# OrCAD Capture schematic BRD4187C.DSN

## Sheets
1 02: RF, Antenna and Power: size A3; title: EFR32xG24B 2.4 GHz 20 dBm Radio Board; rev: A01; company: Silicon Labs; note: BRD4187C
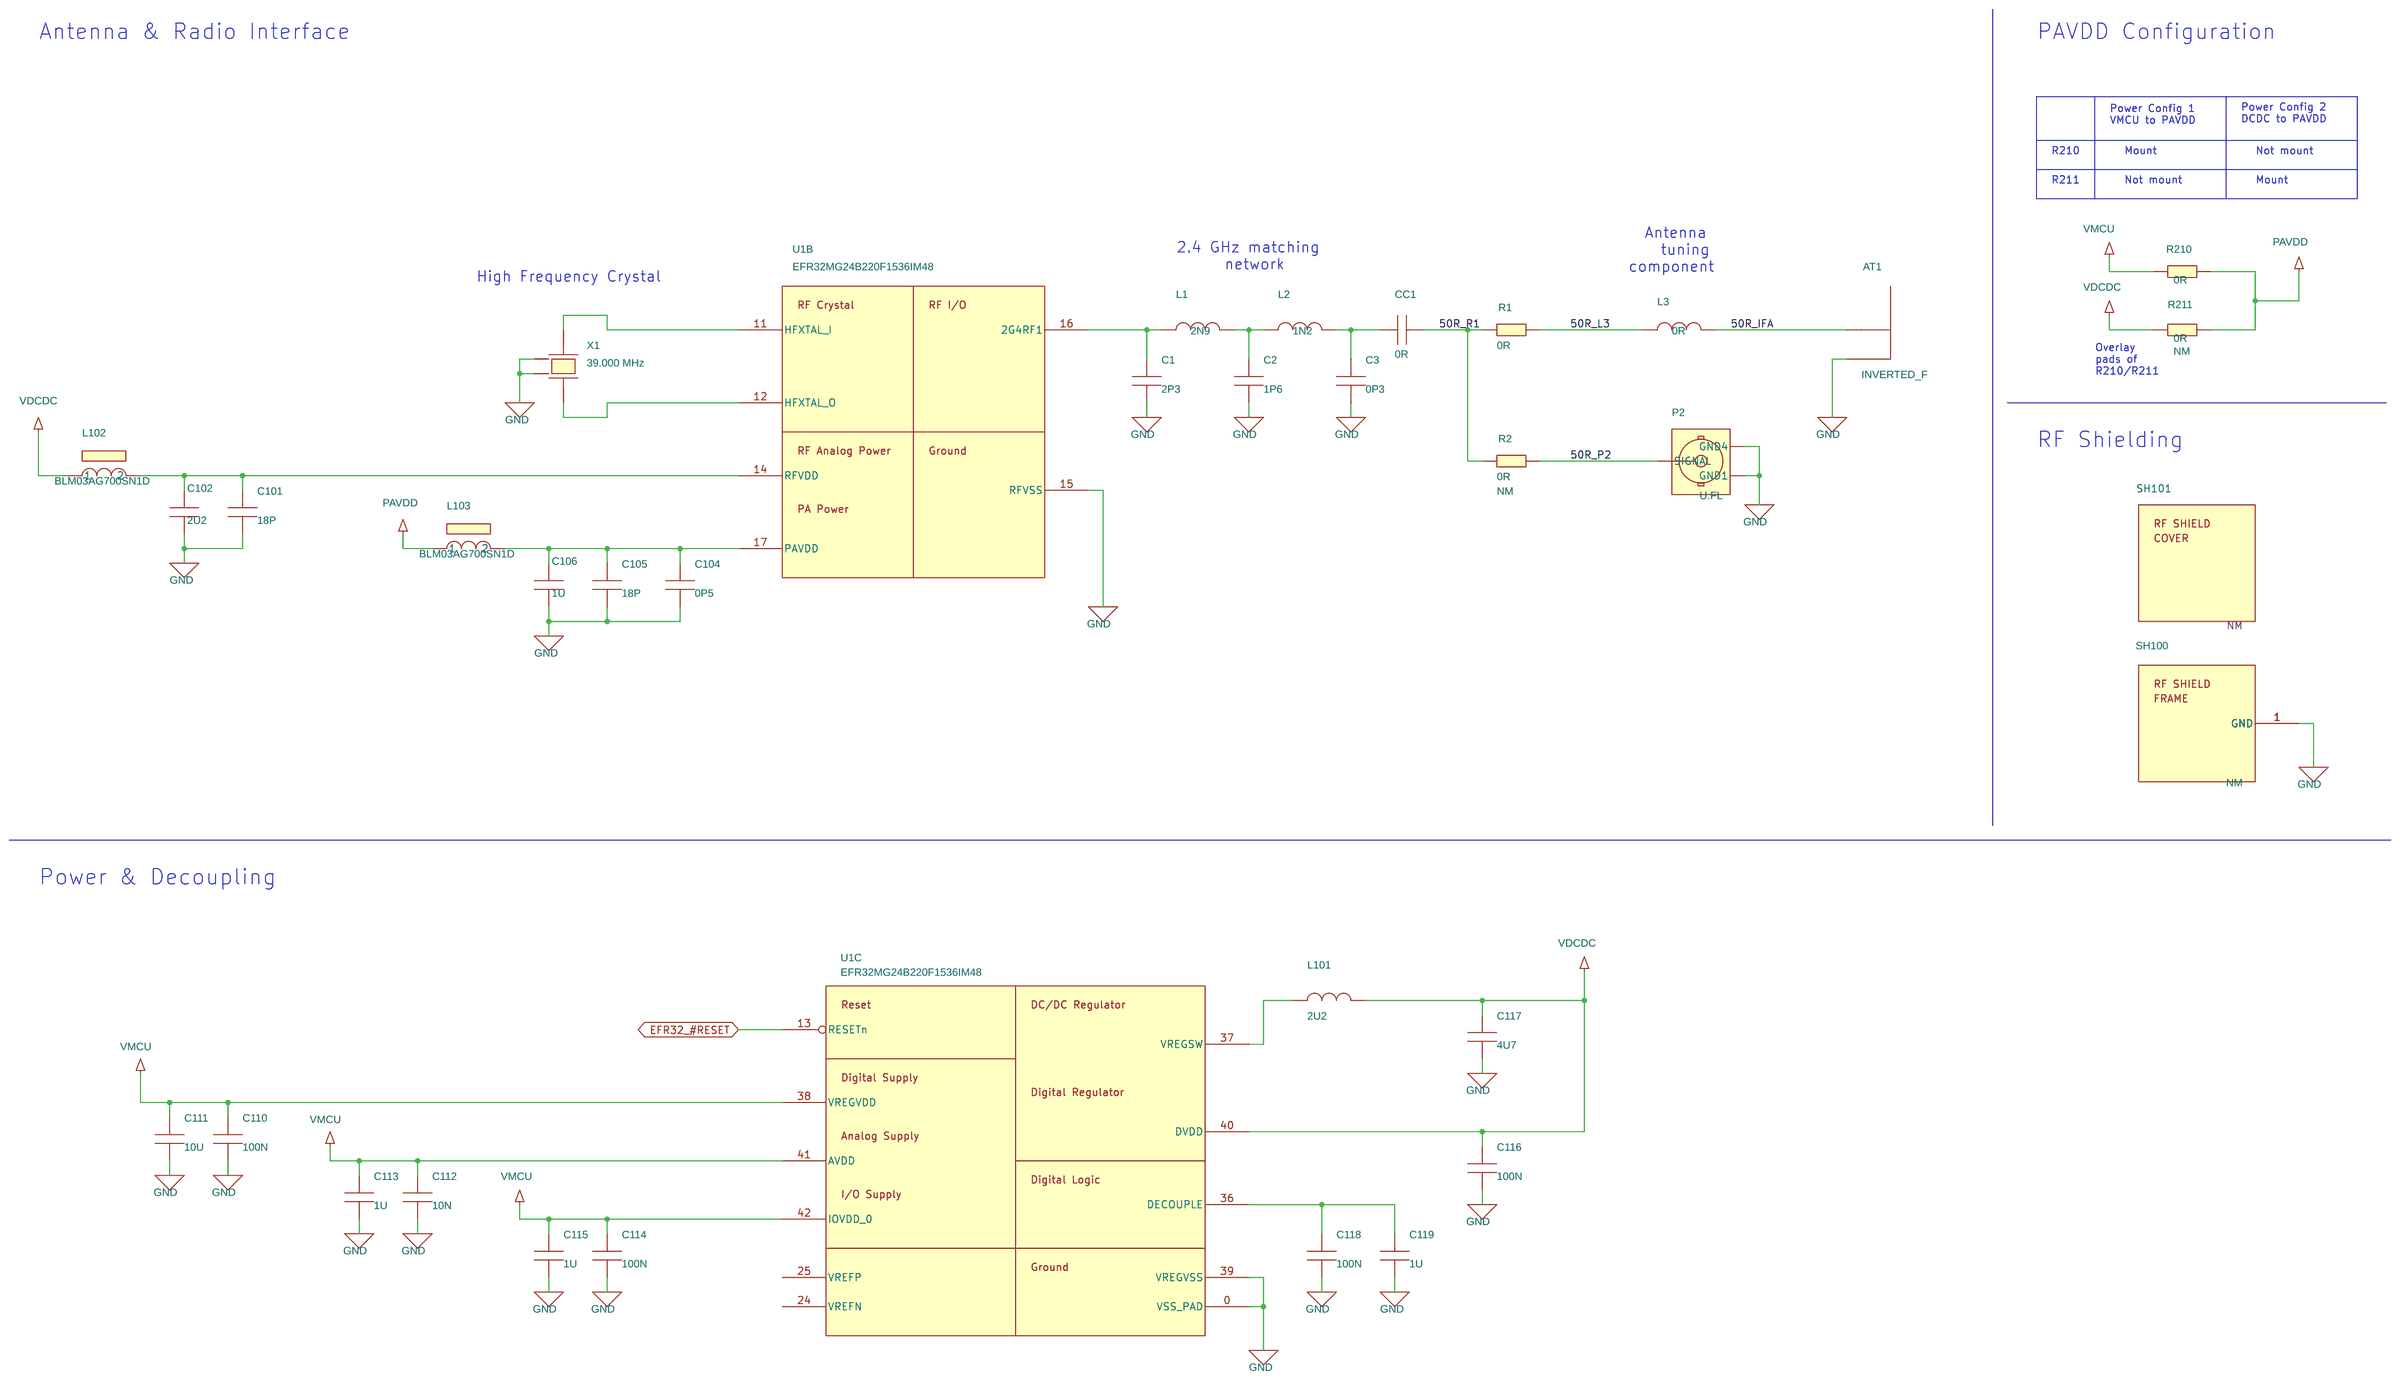
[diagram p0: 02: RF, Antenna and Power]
2 01: Title Page
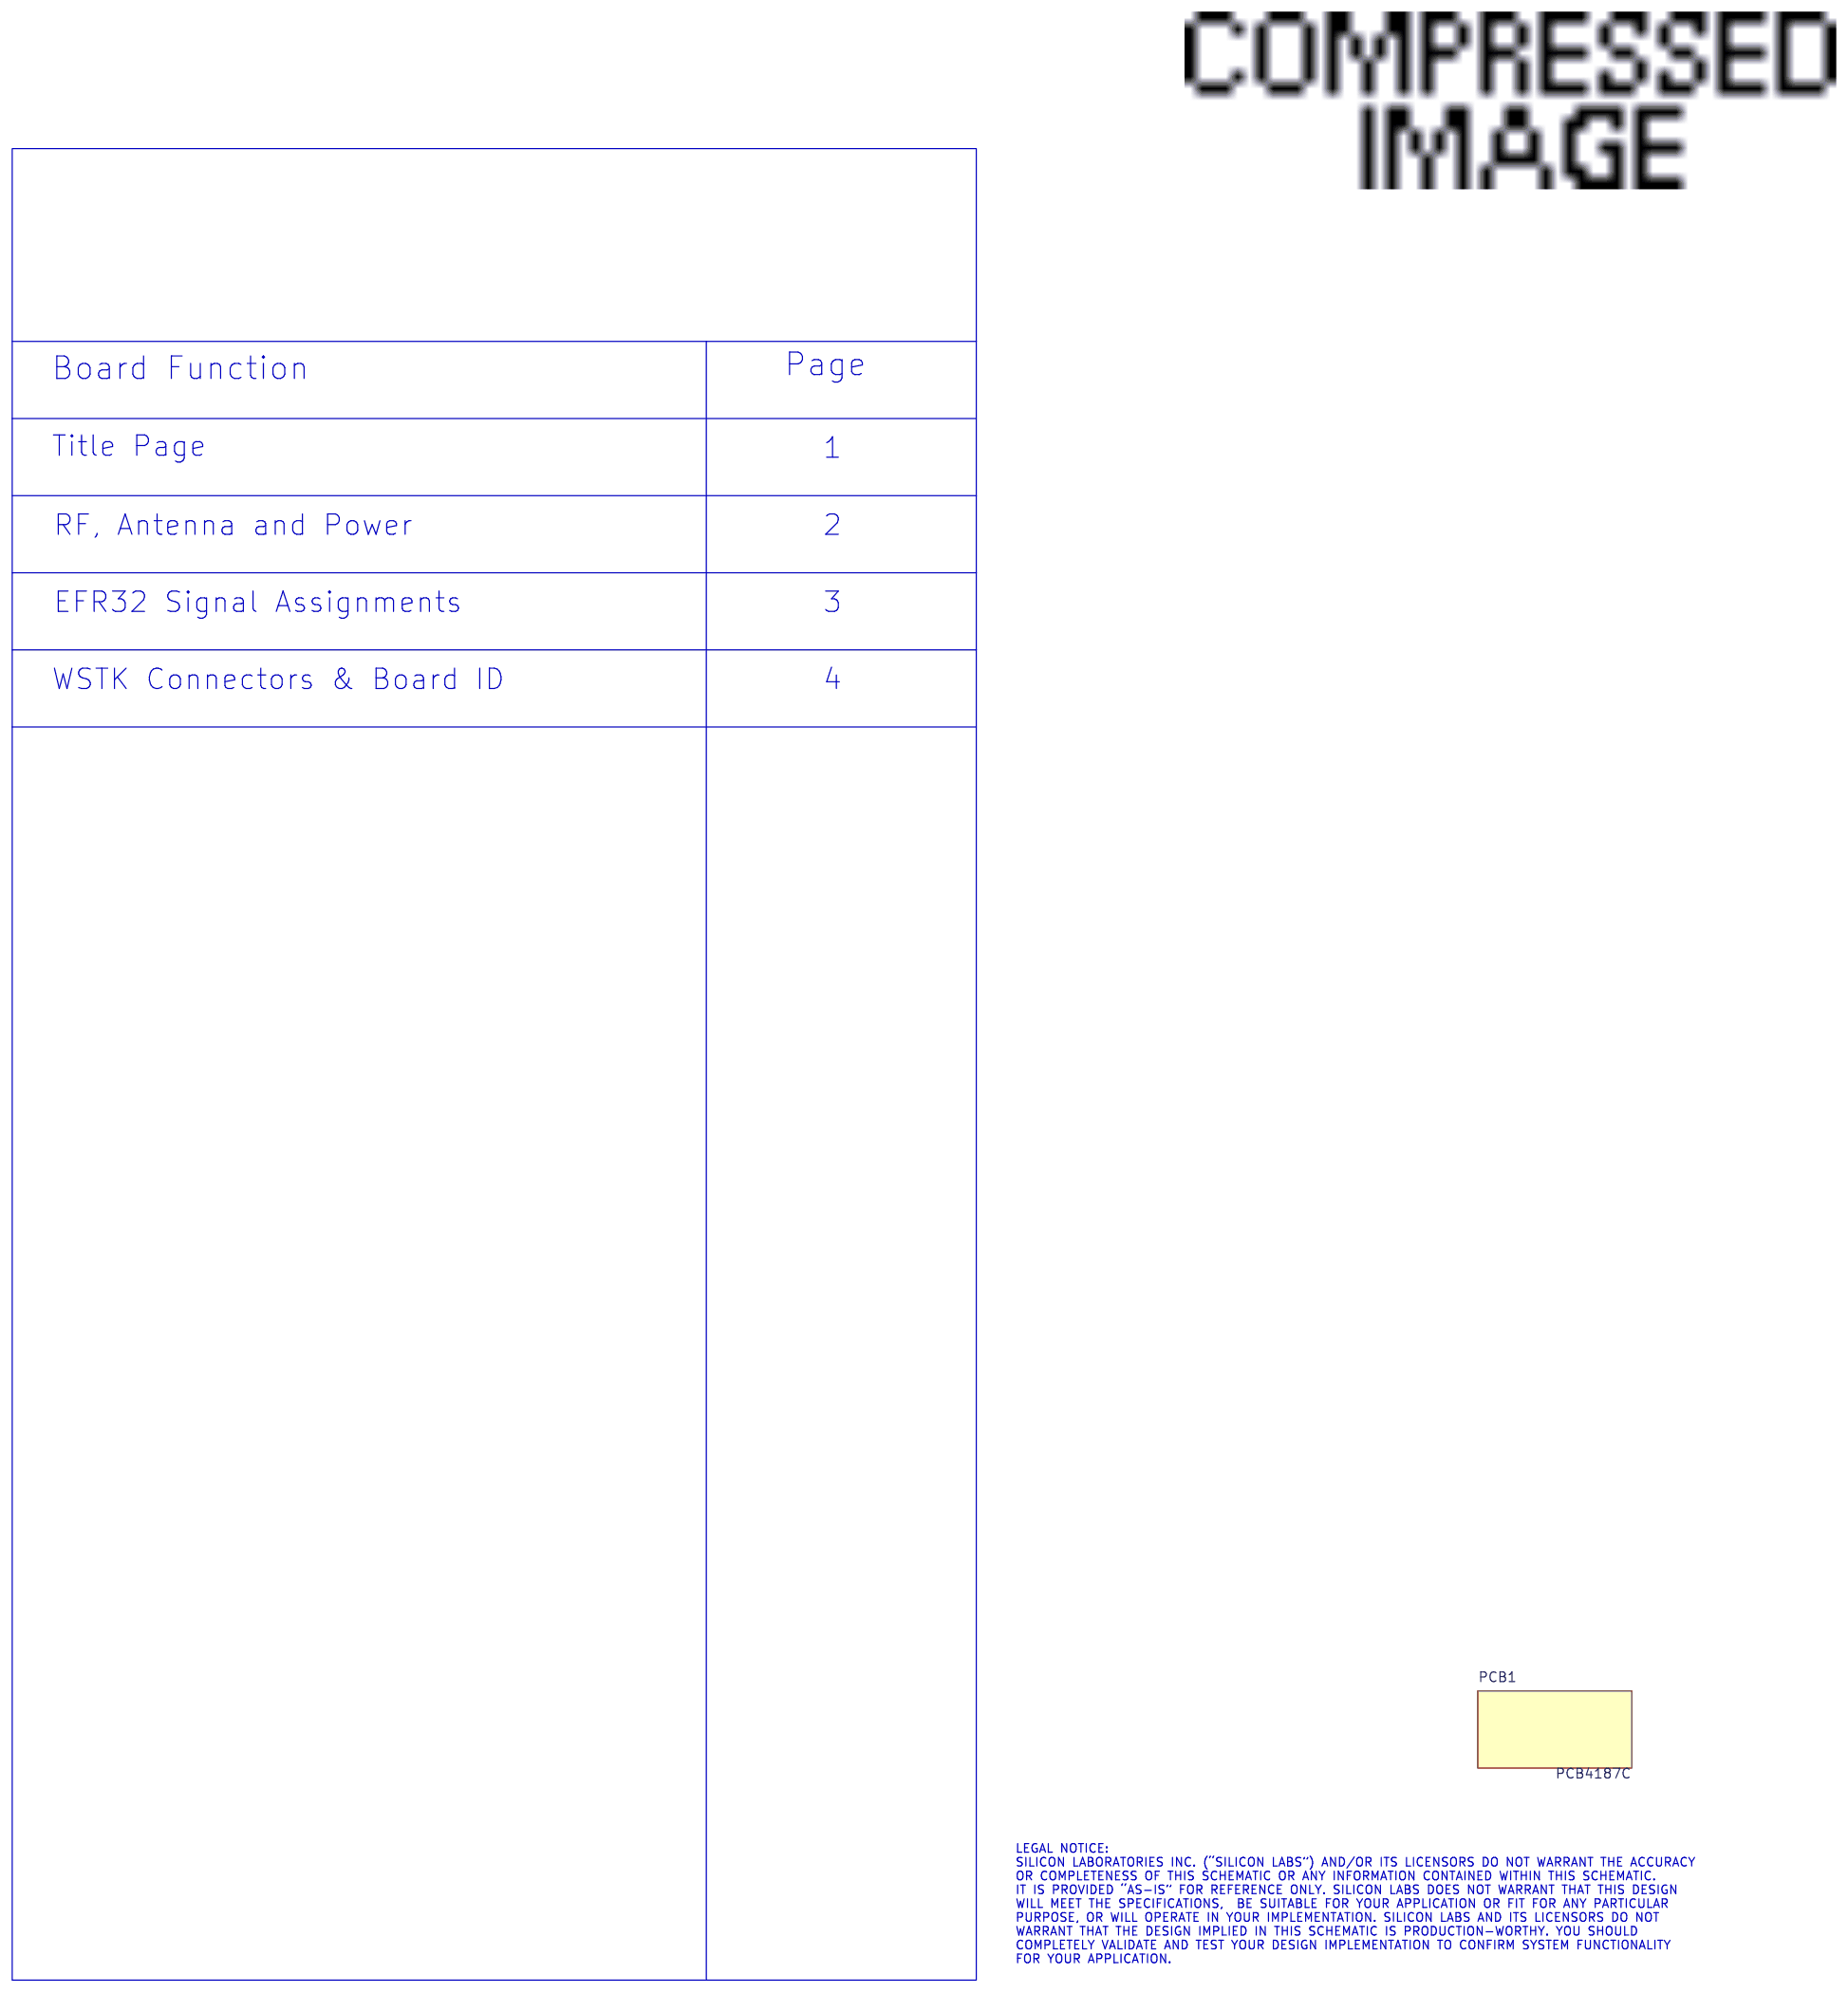
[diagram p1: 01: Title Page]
3 03: EFR32 Signal Assignments: size A3
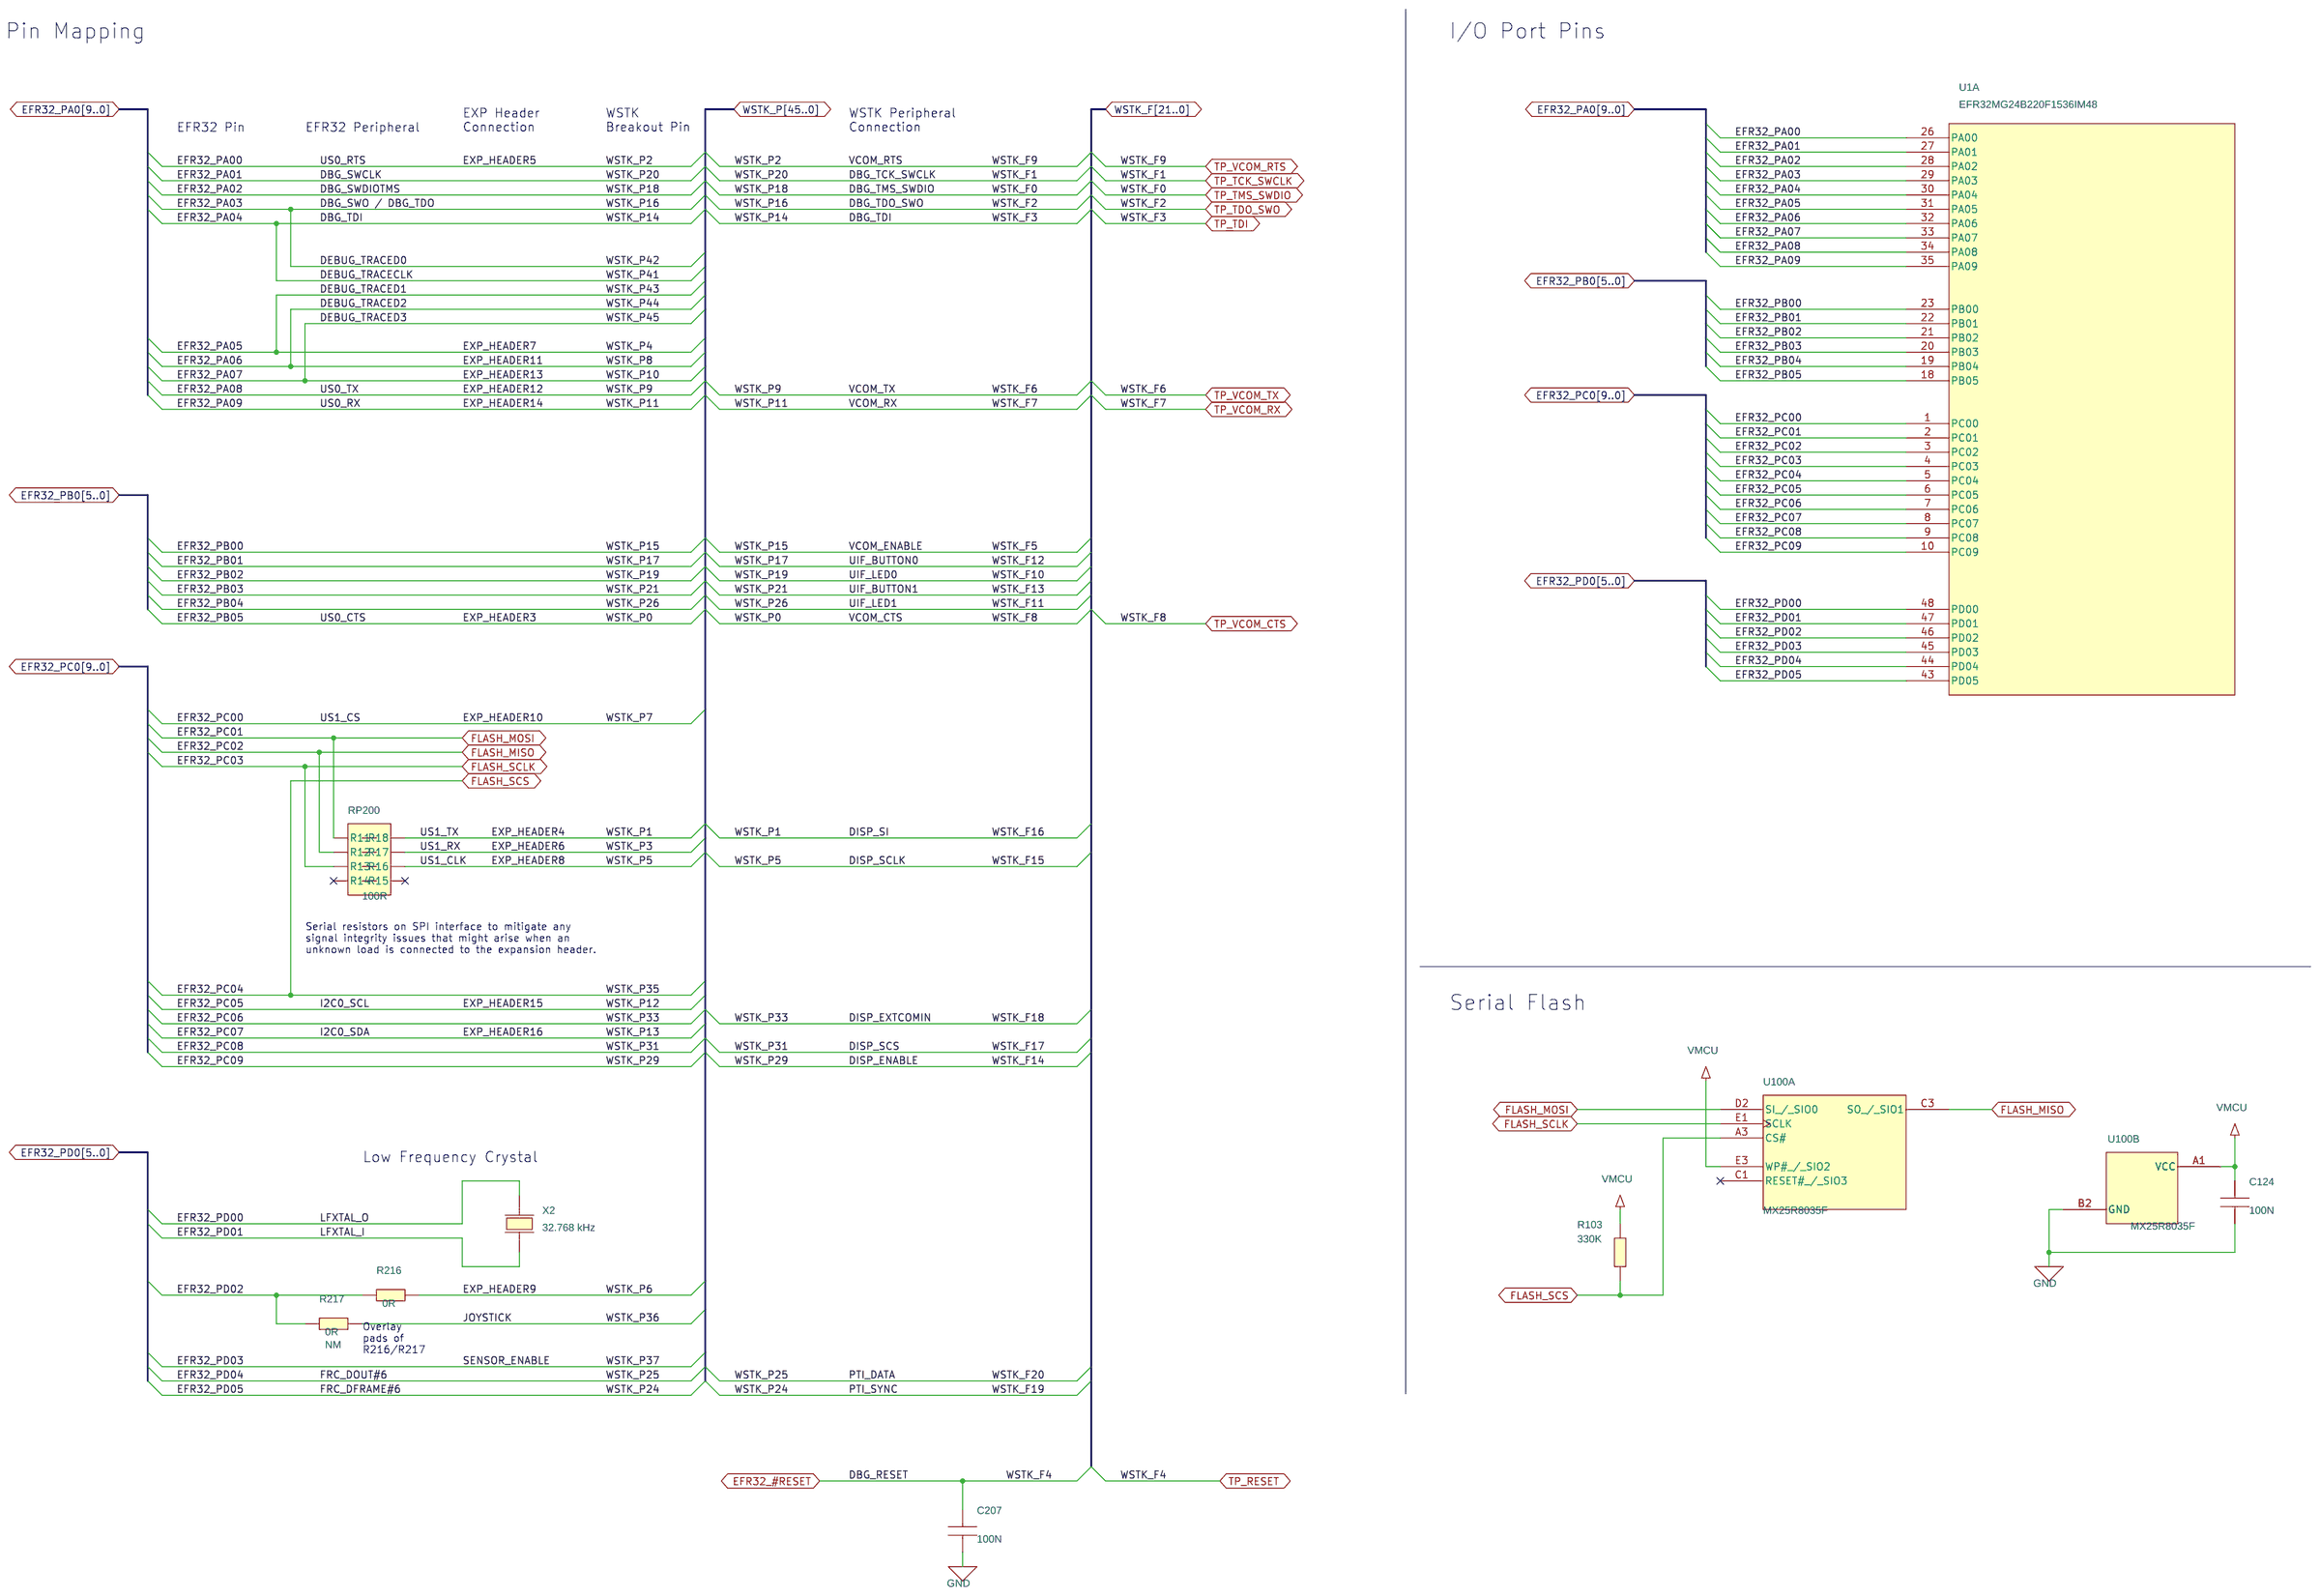
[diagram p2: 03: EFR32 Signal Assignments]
4 04: WSTK Connectors & Board ID: size A3
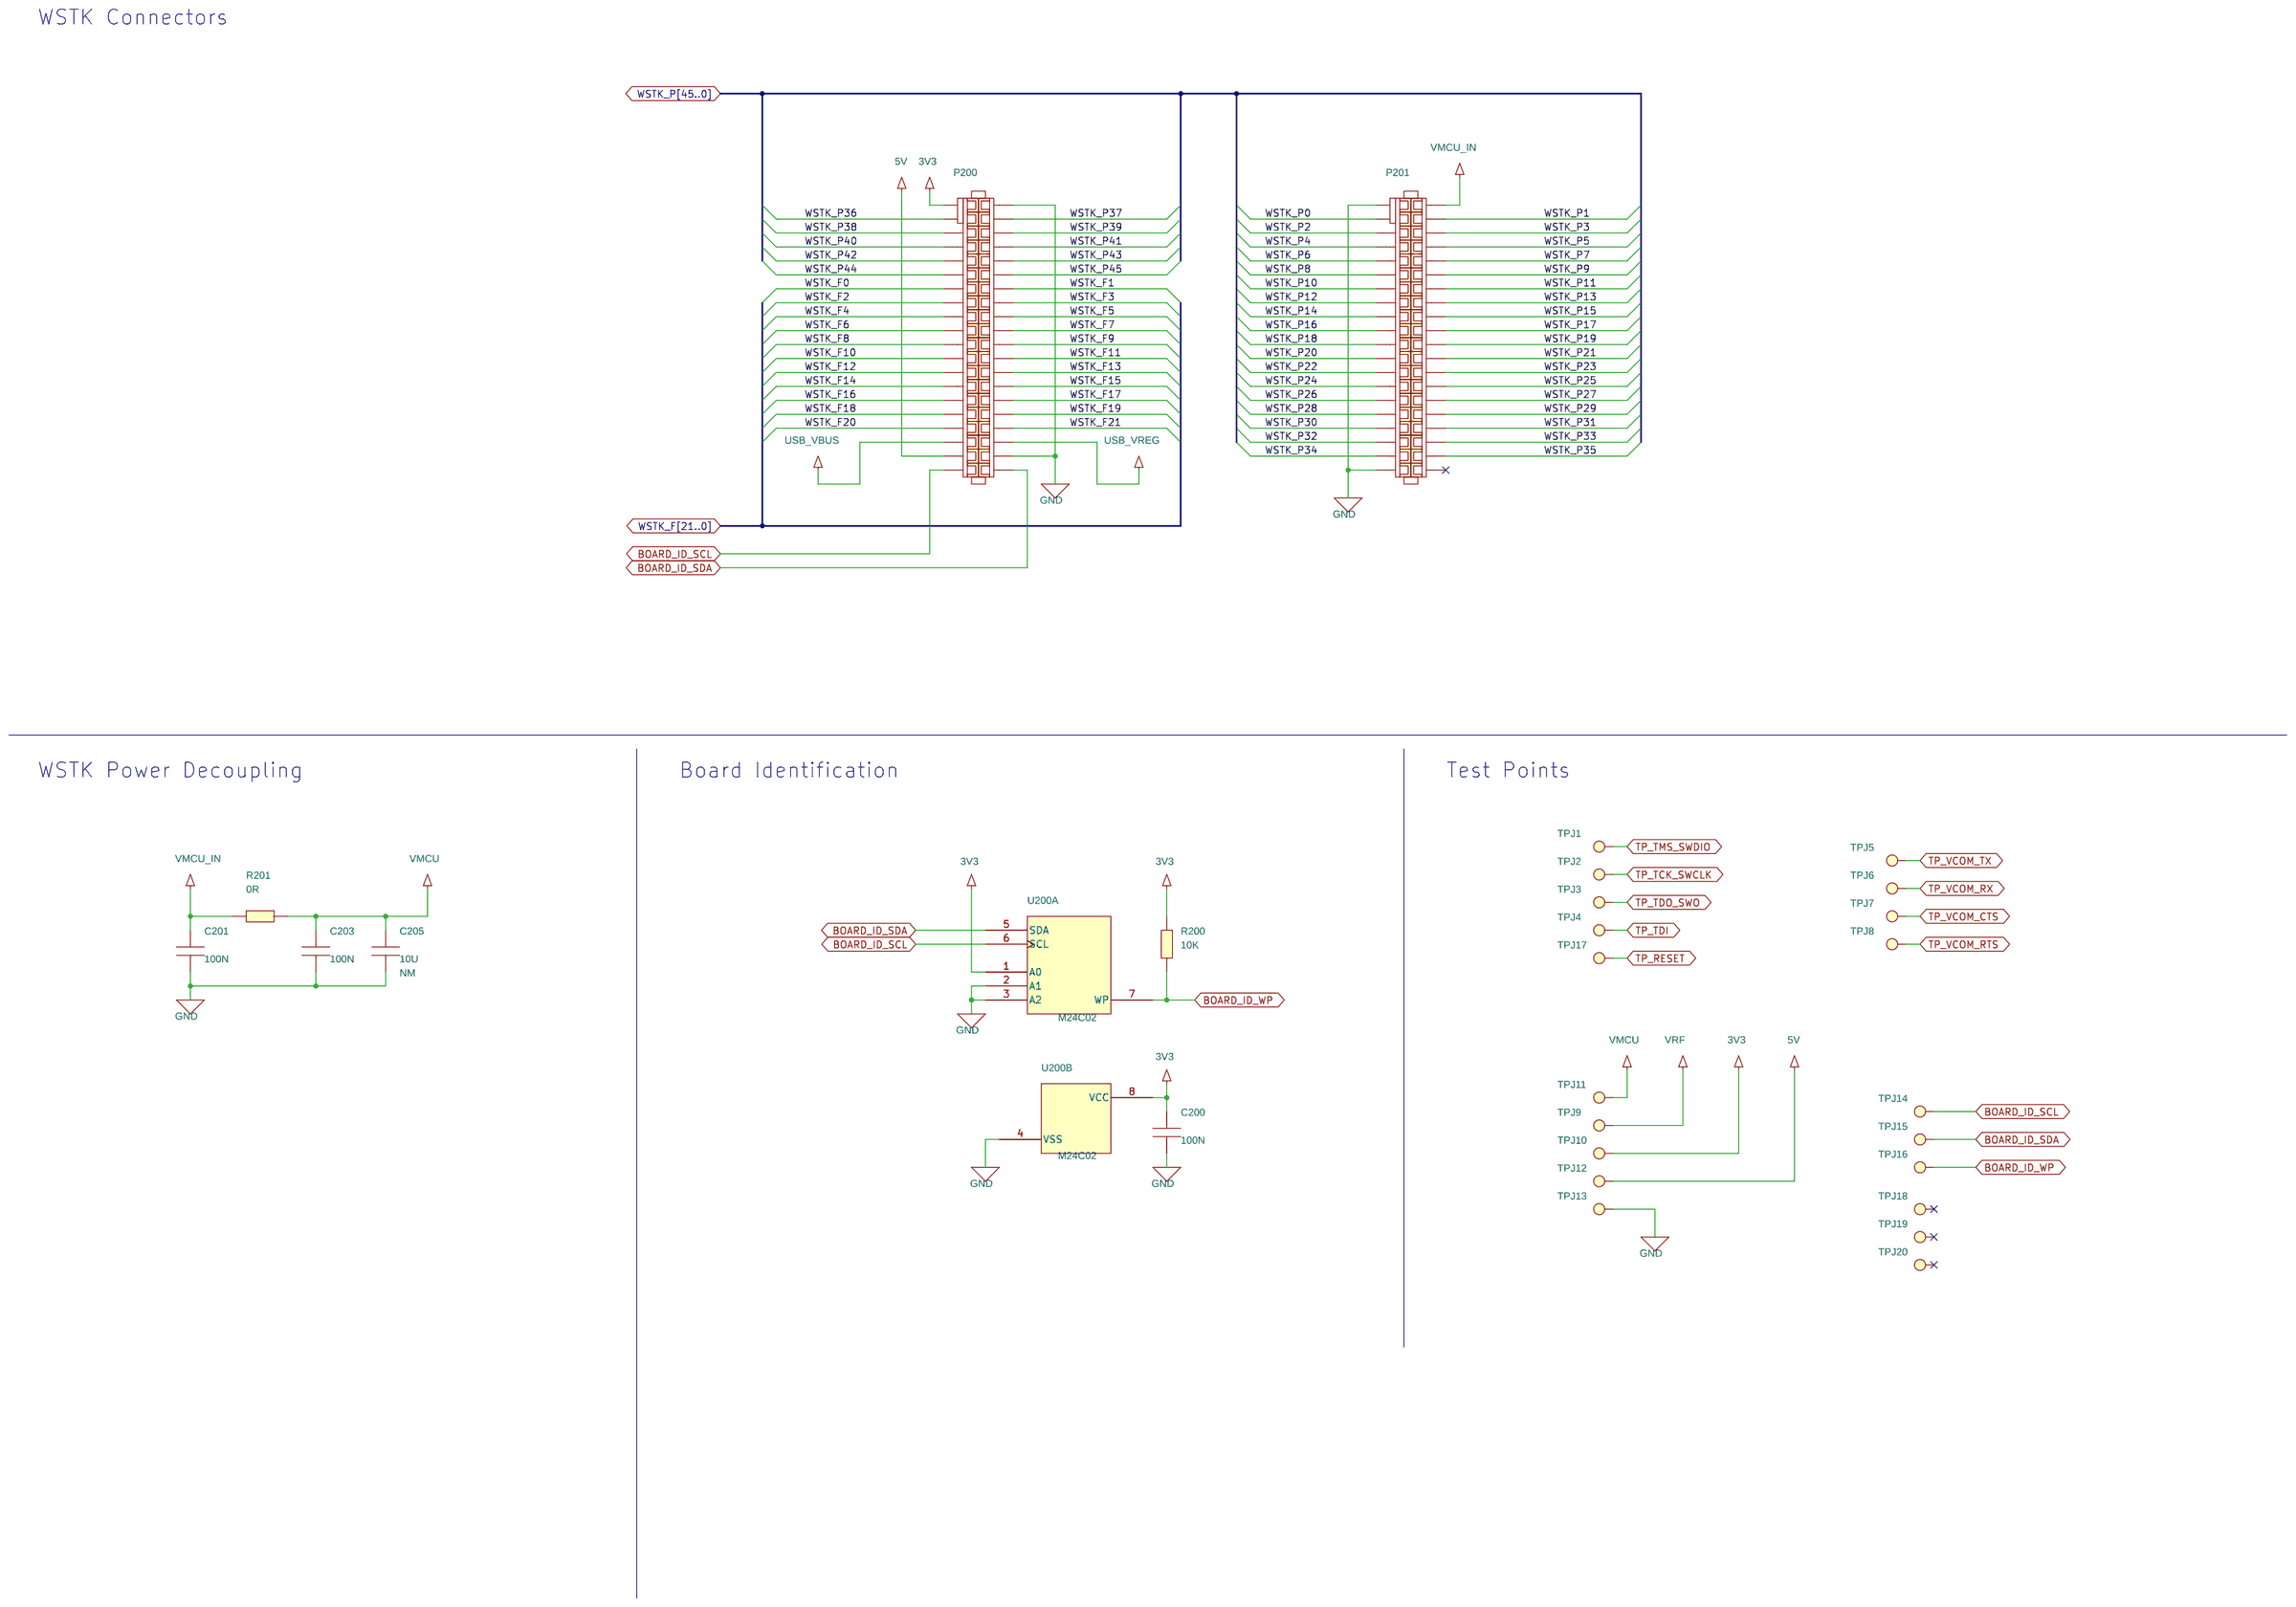
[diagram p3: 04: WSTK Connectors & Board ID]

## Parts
sheet 01: Title Page
PCB1  PCB4187C  [N/A]
sheet 02: RF, Antenna and Power
AT1  INVERTED_F  [EM358x_INVERTED_F]
C1  2P3  [C0201_L]
C2  1P6  [C0201_L]
C3  0P3  [C0201_L]
C101  18P  [C0201_L]
C102  2U2  [C0402_L]
C104  0P5  [C0201_L]
C105  18P  [C0201_L]
C106  1U  [C0402_L]
C110  100N  [C0201_L]
C111  10U  [C0603_L]
C112  10N  [C0201_L]
C113  1U  [C0402_L]
C114  100N  [C0201_L]
C115  1U  [C0402_L]
C116  100N  [C0201_L]
C117  4U7  [C0603_L]
C118  100N  [C0201_L]
C119  1U  [C0402_L]
CC1  0R  [C0201_L]
L1  2N9  [COIL_0201_L]
L2  1N2  [COIL_0201_L]
L3  0R  [COIL_0402_L]
L101  2U2  [COIL_1008_L]
L102  BLM03AG700SN1D  [COIL_MUR_BLM03_0201]
L103  BLM03AG700SN1D  [COIL_MUR_BLM03_0201]
P2  U.FL  [HIROSE_U.FL-R-SMT-1]
R1  0R  [R0402_L]
R2  0R  [R0402_L]
R210  0R  [R0402_L]
R211  0R  [R0402_L]
SH100  RF_SHIELD_FRAME_BMI-S-202-F  [Laird_BMI-S-202-F]
SH101  RF_SHIELD_COVER_BMI-S-202-C
X1  39.000 MHz  [KDS_DSX211SH_2016]
sheet 03: EFR32 Signal Assignments
C124  100N  [C0201_L]
C207  100N  [C0201_L]
R103  330K  [R0201_L]
R216  0R  [R0402_L]
R217  0R  [R0402_L]
RP200  100R  [RES_MNR04-8]
U1  EFR32MG24B220F1536IM48  [QFN48_M040_6.0X6.0_EP_SL]  (sections A,B,C)
U100  MX25R8035F  [BGA8_M040_1.24x1.75_WLCSP]  (sections A,B)
X2  32.768 kHz  [CRYSTAL_MCS_CM8V-T1A_Narrow]
sheet 04: WSTK Connectors & Board ID
C200  100N  [C0201_L]
C201  100N  [C0201_L]
C203  100N  [C0201_L]
C205  10U  [C0805_L]
P200  SOCKET_WCON_2X20_1.27MM_SMD  [SAM_SFC-120-T2-D-A-2X20_SNUM]
P201  SOCKET_WCON_2X20_1.27MM_SMD  [SAM_SFC-120-T2-D-A-2X20_SNUM]
R200  10K  [R0201_L]
R201  0R  [R0402_L]
TPJ1  TPJ_SMD  [TP_1.0_SMD]
TPJ2  TPJ_SMD  [TP_1.0_SMD]
TPJ3  TPJ_SMD  [TP_1.0_SMD]
TPJ4  TPJ_SMD  [TP_1.0_SMD]
TPJ5  TPJ_SMD  [TP_1.0_SMD]
TPJ6  TPJ_SMD  [TP_1.0_SMD]
TPJ7  TPJ_SMD  [TP_1.0_SMD]
TPJ8  TPJ_SMD  [TP_1.0_SMD]
TPJ9  TPJ_SMD  [TP_1.0_SMD]
TPJ10  TPJ_SMD  [TP_1.0_SMD]
TPJ11  TPJ_SMD  [TP_1.0_SMD]
TPJ12  TPJ_SMD  [TP_1.0_SMD]
TPJ13  TPJ_SMD  [TP_1.0_SMD]
TPJ14  TPJ_SMD  [TP_1.0_SMD]
TPJ15  TPJ_SMD  [TP_1.0_SMD]
TPJ16  TPJ_SMD  [TP_1.0_SMD]
TPJ17  TPJ_SMD  [TP_1.0_SMD]
TPJ18  TPJ_SMD  [TP_1.0_SMD]
TPJ19  TPJ_SMD  [TP_1.0_SMD]
TPJ20  TPJ_SMD  [TP_1.0_SMD]
U200  M24C02  [8-TDFN]  (sections A,B)

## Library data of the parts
PCB1 = PCB: Mfg #: PCB4187C Rev. A01; Price_1K: 1.25
AT1 = INVERTED_F
C1 = C0201: Mfg: Murata; Mfg #: GRM0335C1H2R3WA01D; Technology: C0G; Tolerance: ±0.05P
C2 = C0201: Mfg: Murata; Mfg #: GRM0335C1H1R6WA01D; Technology: C0G; Tolerance: ±0.05P
C3 = C0201: Mfg: Murata; Mfg #: GRM0335C1HR30WA01D; Technology: C0G; Tolerance: ±0.05P
C101 = C0201: Rating: 50V; Technology: C0G; Tolerance: 5%
C102 = C0402: Rating: 6.3V; Technology: X7S; Tolerance: 10%
C104 = C0201: Mfg: Murata; Mfg #: GRM0335C1HR50WA01; Rating: 50V; Technology: C0G; Tolerance: +/-0.05P
C105 = C0201: Rating: 50V; Technology: C0G; Tolerance: ±5%
C106 C113 C115 C119 = C0402: Rating: 6.3V; Technology: X7R; Tolerance: 10%
C110 C114 C116 C118 C124 C200 C201 C203 C207 = C0201: Rating: 16V; Technology: X7S; Tolerance: 20%
C111 = C0603: Rating: 25V; Technology: X5R; Tolerance: 20%
C112 = C0201: Rating: 10V; Technology: X5R; Tolerance: 10%
C117 = C0603: Rating: 6.3V; Technology: X5R; Tolerance: 20%
CC1 = C0201
L1 = L0201: Mfg: Murata; Mfg #: LQP03HQ2N9B02D; Tolerance: ±0.1N
L2 = L0201: Mfg: Murata; Mfg #: LQP03HQ1N2W02D; Tolerance: ±0.05N
L3 = INDUCTOR
L101 = L1008: Mfg: Murata; Mfg #: DFE2HCAH2R2MJ0L; Tolerance: +/-20%
L102 = BLM03AX
L103 = BLM03AX_1
P2 = KLS_U.FL
R1 R201 = RESISTOR
R2 = RESISTOR: Not Mounted: NM
R210 R216 = R0402
R211 R217 = R0402: Not Mounted: NM
SH100 = RF_SHIELD_FRAME_BMI-S-202-F: Not Mounted: NM
SH101 = RF_SHIELD_COVER_BMI-S-202-C: Not Mounted: NM
X1 = DSX211SH: Mfg: TXC; Mfg #: 8Y39072002; Price_1K: 0.512
R103 R200 = R0201
RP200 = MNR04M0APJ101
U1 = EFR32xG24_QFN48_LP: Mfg #: EFR32MG24B220F1536IM48-BR
U100 = MX25R8035
X2 = CM8V-T1A: Mfg: Micro Crystal AG; Mfg #: CM8V-T1A-32.768KHZ-7PF-20PPM-TA-QC
C205 = CAPACITOR: Not Mounted: NM; Technology: X5R
P200 P201 = SOCKET_WCON_2X20_1.27MM_SMD: Mfg #: 2344-220MS3CUNR6
TPJ1-TPJ20 = TPJ_SMD
U200 = 24AA024: Mfg: ST Microelectronics; Mfg #: M24C02-FMC6TG; Price_1K: 0.26

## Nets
3V3: C200.1 P200.1 R200.2 TPJ10.1(TP) U200.1(A0) U200.8(VCC)
5V: P200.37 TPJ12.1(TP)
GND: AT1.2(GND) C1.2 C2.2 C3.2 C101.2 C102.2 C104.2 C105.2 C106.2 C110.2 C111.2 C112.2 C113.2 C114.2 C115.2 C116.2 C117.2 C118.2 C119.2 C124.2 C200.2 C201.2 C203.2 C205.2 C207.2 P2.2(GND1) P2.3(GND4) P200.2 P200.38 P201.1 P201.39 SH100.1(GND) TPJ13.1(TP) U1.0(VSS_PAD) U1.15(RFVSS) U1.39(VREGVSS) U100.B2(GND) U200.2(A1) U200.3(A2) U200.4(VSS) X1.2 X1.4
50R_IFA: AT1.1(ANT) L3.2
50R_L3: L3.1 R1.2
50R_P2: P2.1(SIGNAL) R2.2
50R_R1: CC1.2 R1.1 R2.1
BOARD_ID_SCL: P200.39 TPJ14.1(TP) U200.6(SCL)
BOARD_ID_SDA: P200.40 TPJ15.1(TP) U200.5(SDA)
BOARD_ID_WP: R200.1 TPJ16.1(TP) U200.7(WP)
EFR32_#RESET: C207.1 P200.17 TPJ17.1(TP) U1.13(RESETn)
EFR32_PA00: P200.22 P201.5 TPJ8.1(TP) U1.26(PA00)
EFR32_PA01: P200.14 P201.23 TPJ2.1(TP) U1.27(PA01)
EFR32_PA02: P200.13 P201.21 TPJ1.1(TP) U1.28(PA02)
EFR32_PA03: P200.9 P200.15 P201.19 TPJ3.1(TP) U1.29(PA03)
EFR32_PA04: P200.8 P200.16 P201.17 TPJ4.1(TP) U1.30(PA04)
EFR32_PA05: P200.10 P201.7 U1.31(PA05)
EFR32_PA06: P200.11 P201.11 U1.32(PA06)
EFR32_PA07: P200.12 P201.13 U1.33(PA07)
EFR32_PA08: P200.19 P201.12 TPJ5.1(TP) U1.34(PA08)
EFR32_PA09: P200.20 P201.14 TPJ6.1(TP) U1.35(PA09)
EFR32_PB00: P200.18 P201.18 U1.23(PB00)
EFR32_PB01: P200.25 P201.20 U1.22(PB01)
EFR32_PB02: P200.23 P201.22 U1.21(PB02)
EFR32_PB03: P200.26 P201.24 U1.20(PB03)
EFR32_PB04: P200.24 P201.29 U1.19(PB04)
EFR32_PB05: P200.21 P201.3 TPJ7.1(TP) U1.18(PB05)
EFR32_PC00: P201.10 U1.1(PC00)
EFR32_PC01: RP200.1(R11) U1.2(PC01) U100.D2(SI_/_SIO0)
EFR32_PC02: RP200.2(R12) U1.3(PC02) U100.C3(SO_/_SIO1)
EFR32_PC03: RP200.3(R13) U1.4(PC03) U100.E1(SCLK)
EFR32_PC04: P201.38 R103.1 U1.5(PC04) U100.A3(CS#)
EFR32_PC05: P201.15 U1.6(PC05)
EFR32_PC06: P200.31 P201.36 U1.7(PC06)
EFR32_PC07: P201.16 U1.8(PC07)
EFR32_PC08: P200.30 P201.34 U1.9(PC08)
EFR32_PC09: P200.27 P201.32 U1.10(PC09)
EFR32_PD00: U1.48(PD00) X2.1
EFR32_PD01: U1.47(PD01) X2.2
EFR32_PD02: R216.1 R217.1 U1.46(PD02)
EFR32_PD03: P200.4 U1.45(PD03)
EFR32_PD04: P200.33 P201.28 U1.44(PD04)
EFR32_PD05: P200.32 P201.27 U1.43(PD05)
PAVDD: L103.1 R210.1 R211.2
USB_VBUS: P200.35
USB_VREG: P200.36
VDCDC: C116.1 C117.1 L101.2 L102.1 R211.1 U1.40(DVDD)
VMCU: C110.1 C111.1 C112.1 C113.1 C114.1 C115.1 C124.1 C203.1 C205.1 R103.2 R201.2 R210.2 TPJ11.1(TP) U1.38(VREGVDD) U1.41(AVDD) U1.42(IOVDD_0) U100.A1(VCC) U100.E3(WP#_/_SIO2)
VMCU_IN: C201.1 P201.2 R201.1
VREFN: U1.24(VREFN)
VREFP: U1.25(VREFP)
VRF: TPJ9.1(TP)
WSTK_F15: P200.28 P201.8 RP200.6(R16)
WSTK_F16: P200.29 P201.4 RP200.8(R18)
WSTK_F21: P200.34
WSTK_P3: P201.6 RP200.7(R17)
WSTK_P6: P201.9 R216.2
WSTK_P22: P201.25
WSTK_P23: P201.26
WSTK_P27: P201.30
WSTK_P28: P201.31
WSTK_P30: P201.33
WSTK_P32: P201.35
WSTK_P34: P201.37
WSTK_P36: P200.3 R217.2
WSTK_P38: P200.5
WSTK_P39: P200.6
WSTK_P40: P200.7
N17597956: L101.1 U1.37(VREGSW)
N17597974: U1.11(HFXTAL_I) X1.3
N17598005: U1.12(HFXTAL_O) X1.1
N17598097: C101.1 C102.1 L102.2 U1.14(RFVDD)
N17598121: C104.1 C105.1 C106.1 L103.2 U1.17(PAVDD)
N17598142: C1.1 L1.1 U1.16(2G4RF1)
N17598159: C2.1 L1.2 L2.1
N17598275: C3.1 CC1.1 L2.2
N17598561: C118.1 C119.1 U1.36(DECOUPLE)

Not connected (* = marked no-connect by the designer): P201 40*; RP200 4(R14)* 5(R15)*; TPJ18 1(TP)*; TPJ19 1(TP)*; TPJ20 1(TP)*; U100 C1(RESET#_/_SIO3)*

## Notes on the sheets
sheet 1
- Antenna & Radio Interface
- PAVDD Configuration
- Power Config 1
  VMCU to PAVDD
- Power Config 2
  DCDC to PAVDD
- R210
- Mount
- Not mount
- R211
- Not mount
- Mount
- Antenna
      tuning
  component
- 2.4 GHz matching
        network
- High Frequency Crystal
- Overlay
  pads of
  R210/R211
- RF Shielding
- Power & Decoupling
sheet 2
- Board Function
- Page
- Title Page
- 1
- RF, Antenna and Power
- 2
- EFR32 Signal Assignments
- 3
- WSTK Connectors & Board ID
- 4
- LEGAL NOTICE:
  SILICON LABORATORIES INC. (“SILICON LABS”) AND/OR ITS LICENSORS DO NOT WARRANT THE ACCURACY
  OR COMPLETENESS OF THIS SCHEMATIC OR ANY INFORMATION CONTAINED WITHIN THIS SCHEMATIC.
  IT IS PROVIDED “AS-IS” FOR REFERENCE ONLY. SILICON LABS DOES NOT WARRANT THAT THIS DESIGN
  WILL MEET THE SPECIFICATIONS,  BE SUITABLE FOR YOUR APPLICATION OR FIT FOR ANY PARTICULAR
  PURPOSE, OR WILL OPERATE IN YOUR IMPLEMENTATION. SILICON LABS AND ITS LICENSORS DO NOT
  WARRANT THAT THE DESIGN IMPLIED IN THIS SCHEMATIC IS PRODUCTION-WORTHY. YOU SHOULD
  COMPLETELY VALIDATE AND TEST YOUR DESIGN IMPLEMENTATION TO CONFIRM SYSTEM FUNCTIONALITY
  FOR YOUR APPLICATION.
sheet 3
- Pin Mapping
- I/O Port Pins
- EXP Header
  Connection
- WSTK
  Breakout Pin
- WSTK Peripheral
  Connection
- EFR32 Pin
- EFR32 Peripheral
- Serial resistors on SPI interface to mitigate any
  signal integrity issues that might arise when an
  unknown load is connected to the expansion header.
- Serial Flash
- Low Frequency Crystal
- Overlay
  pads of
  R216/R217
sheet 4
- WSTK Connectors
- WSTK Power Decoupling
- Board Identification
- Test Points
